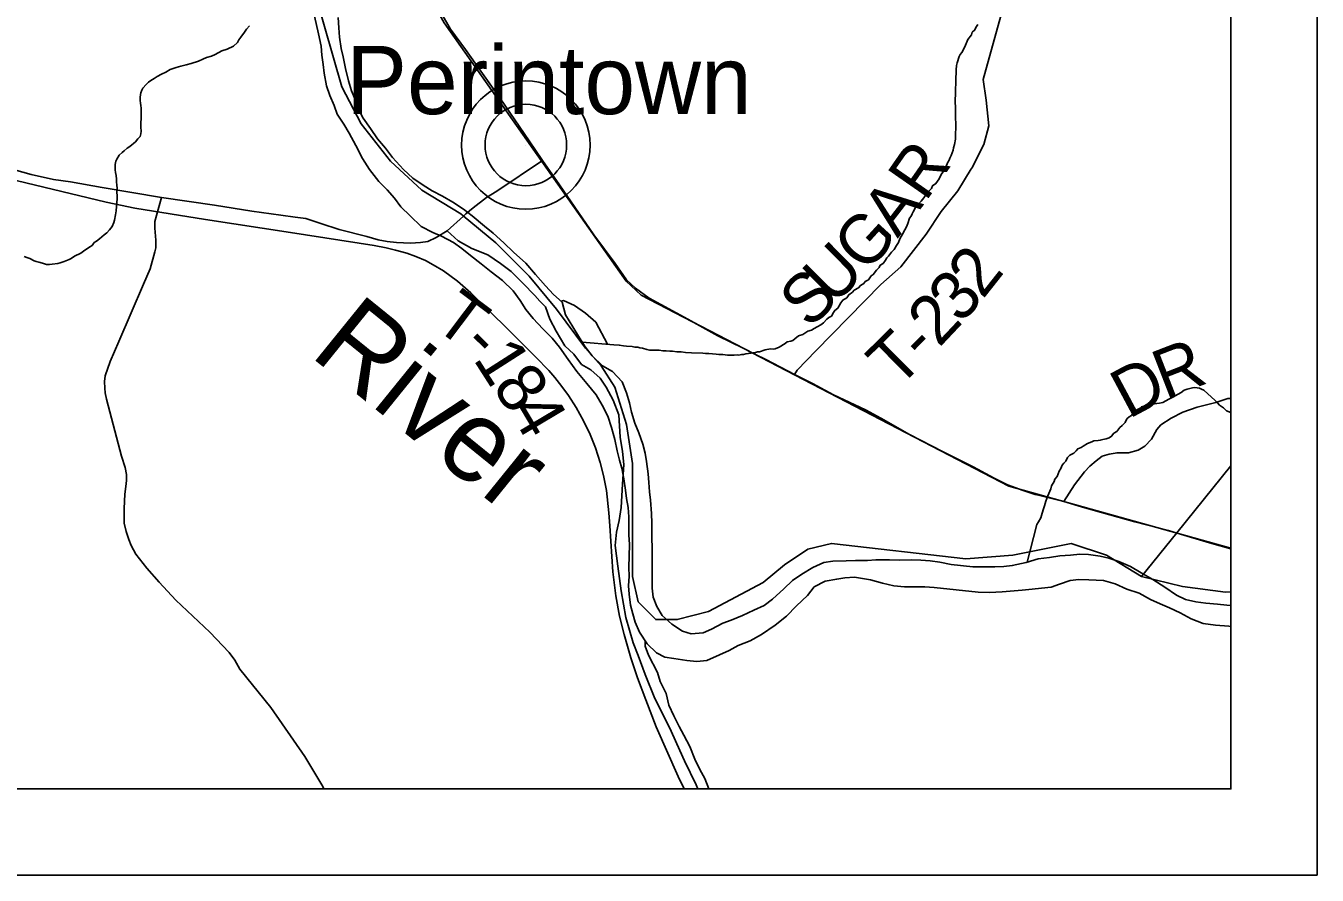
# Model space of a CAD drawing. Extents: x 44.2 to 78.2, y 4.5 to 26.5.
# Drawn here: x 51.74 to 53.236, y 18.501 to 19.485 of the extents above; entities that cross this region are included whole.
import ezdxf

# ---------------------------------------------------------------- set-up
doc = ezdxf.new("R2010")
doc.units = 0
for name, color, linetype in [('GM_X_County_Road', 7, 'Continuous'), ('GM_X_Major_River', 7, 'Continuous'), ('GM_X_Major_River_Text', 7, 'Continuous'), ('GM_X_Minor_River', 7, 'Continuous'), ('GM_X_Rail_Line', 7, 'Continuous'), ('GM_X_Township_Road', 7, 'Continuous'), ('GM_X_Township_Road_Text', 7, 'Continuous'), ('GM_X_Unincorporated', 7, 'Continuous'), ('GM_X_Unincorporated_Location', 7, 'Continuous'), ('GM_X_Unincorporated_Text', 7, 'Continuous'), ('GM_X_US_Route', 7, 'Continuous'), ('SH_Cut_Line', 7, 'Continuous'), ('SH_Data', 7, 'Continuous')]:
    doc.layers.add(name, color=color, linetype=linetype)

msp = doc.modelspace()

# ---------------------------------------------------------------- linework, layer by layer
at = {"layer": 'GM_X_County_Road'}
for points in [[(52.2501, 19.2672), (52.2583, 19.2743), (52.2739, 19.2861), (52.2858, 19.2937), (52.3386, 19.3291)], [(51.7177, 19.3209), (51.7466, 19.3127), (51.7726, 19.3069), (51.7922, 19.3043), (51.8287, 19.2979), (51.8976, 19.2863), (51.959, 19.2772), (52.0023, 19.2703), (52.0358, 19.2658), (52.0524, 19.2635), (52.0645, 19.2618), (52.0821, 19.2562), (52.1033, 19.2492), (52.1352, 19.2409), (52.1484, 19.2372), (52.1589, 19.2351), (52.1696, 19.234), (52.1858, 19.2333), (52.1974, 19.2342), (52.2058, 19.2353), (52.2157, 19.24), (52.2283, 19.2477), (52.2471, 19.2647), (52.2501, 19.2672)], [(52.0854, 18.6014), (52.0844, 18.604), (52.0635, 18.639), (52.0242, 18.6956), (51.9884, 18.7401), (51.9826, 18.7505), (51.976, 18.7594), (51.9535, 18.783), (51.9143, 18.8199), (51.8948, 18.8409), (51.8804, 18.8568), (51.8679, 18.873), (51.8625, 18.8833), (51.8597, 18.8902), (51.8565, 18.8994), (51.8544, 18.9089), (51.8545, 18.926), (51.8549, 18.9427), (51.8562, 18.9517), (51.8572, 18.9586), (51.857, 18.9654), (51.8553, 18.9734), (51.8514, 18.9867), (51.8337, 19.0528), (51.8324, 19.06), (51.8318, 19.0653), (51.8316, 19.0733), (51.8325, 19.0797), (51.8382, 19.0963), (51.8482, 19.1196), (51.8767, 19.186), (51.8843, 19.2037), (51.8897, 19.2233), (51.8909, 19.2278), (51.8908, 19.2369), (51.89, 19.2509), (51.8898, 19.2585), (51.8976, 19.2863)]]:
    msp.add_lwpolyline(points, dxfattribs=at)
at = {"layer": 'GM_X_Major_River'}
for points in [[(52.0746, 19.4963), (52.0795, 19.4757), (52.0823, 19.4615), (52.0833, 19.4512), (52.0846, 19.4402), (52.0859, 19.4303), (52.0887, 19.4154), (52.0926, 19.4043), (52.0974, 19.3928), (52.101, 19.3829), (52.1087, 19.3713), (52.115, 19.3606), (52.1227, 19.3464), (52.1304, 19.3314), (52.1385, 19.3188), (52.1492, 19.3049), (52.1589, 19.2952), (52.1674, 19.2856), (52.1748, 19.2756), (52.1856, 19.2651), (52.1983, 19.2528), (52.2118, 19.2457), (52.2219, 19.2414), (52.2358, 19.2343), (52.2455, 19.2273), (52.2552, 19.2192), (52.2679, 19.2095), (52.2795, 19.2002), (52.2926, 19.1901), (52.3049, 19.1781), (52.313, 19.1669), (52.3196, 19.1565), (52.3278, 19.1461), (52.3393, 19.1342), (52.3501, 19.1234), (52.3586, 19.113), (52.3686, 19.0987), (52.3786, 19.0849), (52.3901, 19.071), (52.4008, 19.0579), (52.4078, 19.0456), (52.4144, 19.033), (52.4187, 19.02), (52.4226, 19.0058), (52.4254, 18.9928), (52.4279, 18.9821), (52.4307, 18.9726), (52.4328, 18.9604), (52.4348, 18.9474), (52.4362, 18.9375), (52.4379, 18.9272), (52.4388, 18.9165), (52.4386, 18.907), (52.4388, 18.8956), (52.4394, 18.8842), (52.4389, 18.8579), (52.4391, 18.8477), (52.4385, 18.8366), (52.4391, 18.8267), (52.4408, 18.8142), (52.4432, 18.8042), (52.4461, 18.7943), (52.4512, 18.7828), (52.46, 18.7694), (52.4708, 18.7589), (52.4806, 18.7538), (52.4908, 18.7525), (52.5059, 18.75), (52.5176, 18.7487), (52.529, 18.75), (52.5439, 18.7566), (52.555, 18.7618), (52.5653, 18.7673), (52.5794, 18.7728), (52.5924, 18.7802), (52.6081, 18.791), (52.6212, 18.8015), (52.6328, 18.8135), (52.6455, 18.8255), (52.6532, 18.8352), (52.6662, 18.8419)], [(52.1022, 19.4947), (52.1028, 19.4829), (52.1037, 19.4719), (52.1057, 19.4589), (52.1078, 19.449), (52.1106, 19.4356), (52.1142, 19.4215), (52.1177, 19.4096), (52.1217, 19.3997), (52.1261, 19.3878), (52.1312, 19.3782), (52.1397, 19.3663), (52.1478, 19.354), (52.1571, 19.3432), (52.1652, 19.3324), (52.1778, 19.3185), (52.1887, 19.3088), (52.2006, 19.3007), (52.2111, 19.294), (52.2231, 19.2878), (52.2351, 19.2807), (52.2471, 19.2726), (52.2572, 19.2652), (52.2717, 19.2532), (52.2818, 19.245), (52.2941, 19.2338), (52.3053, 19.223), (52.3195, 19.2102), (52.3306, 19.1971), (52.3421, 19.184), (52.3514, 19.1739), (52.3614, 19.1649), (52.3654, 19.1505), (52.3738, 19.1363), (52.3815, 19.1236), (52.3882, 19.1133), (52.3963, 19.1029), (52.4082, 19.0913), (52.4199, 19.0846), (52.431, 19.0726), (52.4361, 19.06), (52.4397, 19.0485), (52.4417, 19.0375), (52.4457, 19.0249), (52.4504, 19.0138), (52.4551, 19.0007), (52.4575, 18.9901), (52.4593, 18.9805), (52.4613, 18.9664), (52.4619, 18.9561), (52.4628, 18.9455), (52.4638, 18.9356), (52.465, 18.9203), (52.4652, 18.9089)], [(52.4652, 18.9089), (52.4653, 18.8933), (52.4658, 18.8788), (52.4656, 18.8693), (52.4658, 18.8583), (52.4656, 18.845), (52.4657, 18.8339), (52.4671, 18.8233), (52.471, 18.8126), (52.4773, 18.8022), (52.4885, 18.7921), (52.5008, 18.7839), (52.511, 18.7811), (52.525, 18.782), (52.5346, 18.7865), (52.5476, 18.7931), (52.5571, 18.7968), (52.5705, 18.8023), (52.5835, 18.8082), (52.5953, 18.8137), (52.6053, 18.8211), (52.6184, 18.8331), (52.6284, 18.8428), (52.6391, 18.8499), (52.6518, 18.8577), (52.6647, 18.8636), (52.675, 18.865), (52.6905, 18.8655), (52.7011, 18.8657), (52.7151, 18.8659), (52.7246, 18.8665), (52.7405, 18.8666), (52.7519, 18.8664), (52.7655, 18.8666), (52.7769, 18.8664), (52.7875, 18.8655), (52.7988, 18.8638), (52.812, 18.8613), (52.837, 18.8587), (52.848, 18.8585), (52.8627, 18.8586), (52.873, 18.8589), (52.8828, 18.8599), (52.8988, 18.8634), (52.9129, 18.8678), (52.9258, 18.8695), (52.9379, 18.8712), (52.9501, 18.8721), (52.9611, 18.8731), (52.9709, 18.8729), (52.9845, 18.8708), (52.9947, 18.8684), (53.006, 18.8648), (53.0195, 18.8589), (53.0319, 18.8515), (53.0454, 18.844), (53.0593, 18.8351), (53.0731, 18.8257), (53.0832, 18.8206), (53.0953, 18.8181), (53.107, 18.8164), (53.1203, 18.8151), (53.1312, 18.8142), (53.1359, 18.8137)], [(52.6662, 18.8419), (52.6795, 18.8443), (52.689, 18.8457), (52.7, 18.8467), (52.7185, 18.8434), (52.7325, 18.8397), (52.7457, 18.8365), (52.7578, 18.8355), (52.7699, 18.8353), (52.7816, 18.8355), (52.7922, 18.8346), (52.8433, 18.8293), (52.8565, 18.8287), (52.8709, 18.8296), (52.885, 18.8309), (52.8944, 18.8315), (52.9058, 18.8325), (52.9168, 18.8338), (52.9278, 18.8348), (52.9374, 18.8385), (52.9499, 18.8425), (52.9598, 18.8438), (52.9715, 18.8436), (52.9886, 18.8426), (53.0018, 18.839), (53.0153, 18.8327), (53.0296, 18.8279), (53.0427, 18.8205), (53.054, 18.8157), (53.0649, 18.811), (53.0773, 18.8051), (53.09, 18.7981), (53.1039, 18.7929), (53.1183, 18.7908), (53.1334, 18.7898), (53.1359, 18.7894)]]:
    msp.add_lwpolyline(points, dxfattribs=at)
at = {"layer": 'GM_X_Minor_River'}
for points in [[(52.7743, 19.2786), (52.7771, 19.2819), (52.7802, 19.286), (52.7845, 19.292), (52.7892, 19.2968), (52.7904, 19.2998), (52.7943, 19.3024), (52.7963, 19.305), (52.7982, 19.3079), (52.8006, 19.3128), (52.8034, 19.3173), (52.8042, 19.3195), (52.807, 19.324), (52.8078, 19.3263), (52.8098, 19.3296), (52.8106, 19.3319), (52.8122, 19.3349), (52.8143, 19.3409), (52.8147, 19.3436), (52.816, 19.3477), (52.8169, 19.3537), (52.8174, 19.3731), (52.8171, 19.3769), (52.8172, 19.3799), (52.817, 19.3871), (52.8171, 19.3913), (52.8168, 19.3962), (52.8178, 19.4342), (52.8183, 19.4391), (52.8191, 19.4421), (52.8212, 19.4496), (52.8224, 19.4519), (52.8244, 19.4541), (52.828, 19.4608), (52.8312, 19.4691), (52.8355, 19.4747), (52.8364, 19.4777), (52.8391, 19.4799), (52.8415, 19.4844), (52.843, 19.4866)], [(51.9994, 19.4852), (51.9959, 19.4811), (51.9935, 19.4777), (51.9896, 19.4718), (51.9872, 19.4688), (51.9856, 19.4658), (51.981, 19.4614), (51.9737, 19.4581), (51.9675, 19.456), (51.9595, 19.4517), (51.9556, 19.4499), (51.9495, 19.4485), (51.9453, 19.4464), (51.9403, 19.4442), (51.9319, 19.4414), (51.9261, 19.44), (51.92, 19.4383), (51.9146, 19.4369), (51.9112, 19.4355), (51.9077, 19.4344), (51.9024, 19.4315), (51.8977, 19.429), (51.8927, 19.4265), (51.8889, 19.4239), (51.885, 19.4218), (51.8823, 19.4199), (51.8796, 19.4173), (51.8761, 19.4129), (51.8749, 19.4106), (51.8736, 19.4076), (51.8732, 19.4054), (51.8727, 19.402), (51.873, 19.3985), (51.8733, 19.3955), (51.8736, 19.3928), (51.8739, 19.3898), (51.8739, 19.386), (51.8741, 19.3826), (51.8738, 19.3678), (51.874, 19.3629), (51.8736, 19.3598), (51.8727, 19.3568), (51.87, 19.3542), (51.8676, 19.3509), (51.8607, 19.3454), (51.8576, 19.3432), (51.8545, 19.3402), (51.8521, 19.3384), (51.8486, 19.3351), (51.8459, 19.3306), (51.8447, 19.3283), (51.8438, 19.3246), (51.8437, 19.3215), (51.844, 19.3181), (51.8443, 19.3151), (51.845, 19.3116), (51.8453, 19.3074), (51.8456, 19.304), (51.8459, 19.301), (51.8461, 19.2968), (51.846, 19.2919), (51.8463, 19.2885), (51.8462, 19.2847), (51.8457, 19.2805), (51.8456, 19.2759), (51.8451, 19.2707), (51.8442, 19.2661), (51.8433, 19.2601), (51.8425, 19.2574), (51.8405, 19.2526), (51.8373, 19.2489), (51.8342, 19.2455), (51.8311, 19.2429), (51.8257, 19.2382), (51.8222, 19.2356), (51.8195, 19.2341), (51.8171, 19.2308), (51.8144, 19.229), (51.8074, 19.2242)], [(52.3847, 19.1187), (52.4215, 19.1156), (52.4276, 19.1154), (52.4325, 19.1145), (52.4359, 19.1141), (52.4427, 19.1135), (52.4458, 19.113), (52.4492, 19.1129), (52.4514, 19.1121), (52.4545, 19.1117), (52.4597, 19.1104), (52.4628, 19.1096), (52.4738, 19.1093), (52.4783, 19.1088), (52.4821, 19.1087), (52.4863, 19.1082), (52.4893, 19.1081), (52.4942, 19.1076), (52.4995, 19.1075), (52.5045, 19.1069), (52.5113, 19.1064), (52.5246, 19.106), (52.5276, 19.1056), (52.5314, 19.1055), (52.5356, 19.105), (52.5397, 19.1049), (52.5431, 19.1044), (52.5477, 19.1043), (52.553, 19.1038), (52.5606, 19.1036), (52.564, 19.1039), (52.5663, 19.1038), (52.5694, 19.1045), (52.5716, 19.1044), (52.5743, 19.1051), (52.577, 19.1054), (52.5804, 19.1061), (52.5827, 19.1064), (52.5854, 19.1067), (52.5877, 19.1074), (52.59, 19.1077), (52.5968, 19.1098), (52.6026, 19.1108), (52.606, 19.1107), (52.6083, 19.1111), (52.6129, 19.1128), (52.6198, 19.1172), (52.6221, 19.119), (52.6263, 19.1197), (52.6286, 19.1208), (52.631, 19.1226), (52.6352, 19.1259), (52.6402, 19.1277), (52.646, 19.1313), (52.6502, 19.1327), (52.6533, 19.1346), (52.6568, 19.1364), (52.661, 19.1389), (52.6641, 19.1411), (52.668, 19.1455), (52.6703, 19.1474), (52.6734, 19.1488), (52.6758, 19.1529), (52.6774, 19.1555), (52.6809, 19.1581), (52.6841, 19.1641), (52.6864, 19.1674), (52.691, 19.17), (52.6934, 19.1737), (52.6977, 19.1766), (52.6996, 19.1789), (52.7046, 19.1818), (52.707, 19.1844), (52.7108, 19.1865), (52.7124, 19.1888), (52.7163, 19.191), (52.7194, 19.1954), (52.7217, 19.1969), (52.7257, 19.2021), (52.7288, 19.205), (52.7296, 19.2077), (52.7331, 19.2099), (52.7358, 19.2136), (52.7374, 19.2162), (52.7394, 19.2184), (52.7429, 19.2229), (52.746, 19.2262), (52.7488, 19.2307), (52.7512, 19.2341), (52.7524, 19.2382), (52.7556, 19.2438), (52.7584, 19.2487), (52.7604, 19.2524), (52.762, 19.2562), (52.7637, 19.2622), (52.7656, 19.2648), (52.7668, 19.2674), (52.768, 19.2697), (52.7704, 19.2738), (52.7708, 19.276), (52.7743, 19.2786)], [(51.8074, 19.2242), (51.804, 19.2216), (51.7967, 19.2184), (51.7928, 19.2155), (51.7905, 19.2144), (51.7847, 19.2123), (51.7801, 19.2105), (51.7775, 19.2098), (51.771, 19.2092), (51.7675, 19.2086), (51.7645, 19.2086), (51.7596, 19.2103), (51.7555, 19.2112), (51.7524, 19.212), (51.7502, 19.2128), (51.7449, 19.2156), (51.7415, 19.2168), (51.7385, 19.218)], [(52.36, 19.1662), (52.363, 19.1668), (52.3757, 19.1612), (52.3884, 19.1523), (52.4007, 19.1418), (52.4142, 19.1162)], [(52.9002, 18.8639), (52.9111, 18.9077), (52.9131, 18.9107), (52.9159, 18.9152), (52.9167, 18.9178), (52.9184, 18.9246), (52.92, 18.9291), (52.9217, 18.9344), (52.9241, 18.9408), (52.925, 18.9434), (52.9274, 18.9487), (52.9282, 18.9524), (52.9314, 18.9573), (52.9322, 18.9599), (52.9346, 18.9633), (52.937, 18.9693), (52.939, 18.9723), (52.9406, 18.9764), (52.9426, 18.9786), (52.9449, 18.9808), (52.9469, 18.985), (52.9496, 18.9879), (52.9539, 18.9901), (52.9566, 18.9927), (52.9586, 18.9953), (52.9624, 18.9967), (52.9647, 18.9982), (52.9697, 19.0014), (52.9751, 19.0032), (52.9774, 19.0043), (52.9823, 19.0049), (52.9846, 19.0052), (52.9877, 19.0059), (52.9915, 19.0066), (52.995, 19.008), (52.9977, 19.0098), (53.0004, 19.0132), (53.0039, 19.0153), (53.0074, 19.0198), (53.0101, 19.022), (53.0136, 19.0257), (53.0156, 19.0298), (53.018, 19.0321), (53.0207, 19.0339), (53.0235, 19.038), (53.0258, 19.0398), (53.0292, 19.0409), (53.0323, 19.0438), (53.035, 19.0445), (53.0373, 19.0452), (53.04, 19.0463), (53.0438, 19.0466), (53.0476, 19.0472), (53.0499, 19.0475), (53.0533, 19.0482), (53.0572, 19.0489), (53.0641, 19.0525), (53.0687, 19.055), (53.0749, 19.0586), (53.0783, 19.0604), (53.0818, 19.063), (53.0853, 19.0644), (53.0914, 19.0658), (53.0941, 19.0661), (53.0967, 19.066), (53.0997, 19.0656), (53.102, 19.0644), (53.1046, 19.0632), (53.1091, 19.0589), (53.1131, 19.0554), (53.1176, 19.0511), (53.1206, 19.0483), (53.1228, 19.0456), (53.125, 19.0441), (53.1273, 19.0425), (53.131, 19.0393), (53.1359, 19.0373), (53.1359, 19.0373)], [(52.4577, 18.7729), (52.4578, 18.7666), (52.4617, 18.7563), (52.4719, 18.736), (52.4751, 18.7257), (52.482, 18.7119), (52.4851, 18.6982), (52.491, 18.6859), (52.4971, 18.6737), (52.5026, 18.6637), (52.5092, 18.6503), (52.5153, 18.6358), (52.5211, 18.6239), (52.5266, 18.6132), (52.5313, 18.6014)]]:
    msp.add_lwpolyline(points, dxfattribs=at)
at = {"layer": 'GM_X_Rail_Line'}
for points in [[(52.0567, 19.5883), (52.1063, 19.4143), (52.1289, 19.3714), (52.1628, 19.3285), (52.1989, 19.2946), (52.2441, 19.2675), (52.2468, 19.2652), (52.2848, 19.2336), (52.3232, 19.1952), (52.3548, 19.1568), (52.3887, 19.1116), (52.4067, 19.0912), (52.4226, 19.0664), (52.4361, 19.0234), (52.4429, 18.9783), (52.4429, 18.8472), (52.4496, 18.8179), (52.47, 18.7975), (52.4948, 18.7975), (52.531, 18.8066), (52.5942, 18.8404), (52.6191, 18.8608), (52.6462, 18.8789), (52.6733, 18.8856), (52.8291, 18.8676), (52.8834, 18.8721), (52.9511, 18.8856), (52.9918, 18.8721), (53.0324, 18.8472), (53.0734, 18.898), (53.1359, 18.9756), (53.1359, 25.4014)], [(53.1359, 18.8803), (52.8787, 18.9518), (52.4529, 19.1732), (52.4355, 19.1892), (52.2249, 19.4887), (52.1626, 19.5993), (52.0324, 19.7548), (51.9429, 19.8757), (51.918, 19.9004), (51.8875, 19.9114), (51.8322, 19.9117), (51.7576, 19.9172), (51.6529, 19.9117)], [(48.642, 18.6014), (53.1359, 18.6014), (53.1359, 18.8297), (53.1296, 18.8292), (53.0799, 18.8359), (53.0324, 18.8472), (52.9918, 18.8721), (52.9511, 18.8856), (52.8834, 18.8721), (52.8291, 18.8676), (52.6733, 18.8856), (52.6462, 18.8789), (52.6191, 18.8608), (52.5942, 18.8404), (52.531, 18.8066), (52.4948, 18.7975), (52.47, 18.7975), (52.4496, 18.8179), (52.4429, 18.8472), (52.4429, 18.9783), (52.4361, 19.0234), (52.4226, 19.0664), (52.4067, 19.0912), (52.3887, 19.1116), (52.3548, 19.1568), (52.3232, 19.1952), (52.2848, 19.2336), (52.2468, 19.2652), (52.2441, 19.2675), (52.1989, 19.2946), (52.1628, 19.3285), (52.1289, 19.3714), (52.1063, 19.4143), (52.0567, 19.5883)], [(51.3792, 19.39), (51.8335, 19.2809), (51.8666, 19.274), (51.9485, 19.2609), (52.0469, 19.2457), (52.1439, 19.2305), (52.1578, 19.2278), (52.1687, 19.2254), (52.1815, 19.2219), (52.1921, 19.2179), (52.2031, 19.2132), (52.2122, 19.2084), (52.2243, 19.2013), (52.2403, 19.1893), (52.2557, 19.176), (52.299, 19.1335), (52.3312, 19.1015), (52.3459, 19.086), (52.353, 19.0777), (52.3613, 19.0674), (52.3688, 19.0569), (52.3778, 19.0429), (52.3864, 19.0277), (52.394, 19.0119), (52.4001, 18.9962), (52.4057, 18.9793), (52.4095, 18.9644), (52.413, 18.9468), (52.4157, 18.9212), (52.4168, 18.9061), (52.4203, 18.8526), (52.4238, 18.825), (52.4281, 18.8014), (52.4333, 18.78), (52.4412, 18.753), (52.4489, 18.73), (52.4583, 18.7043), (52.4705, 18.6734), (52.4959, 18.6158), (52.5029, 18.6014)]]:
    msp.add_lwpolyline(points, dxfattribs=at)
msp.add_lwpolyline([(53.1359, 18.8297), (53.1359, 18.9756), (53.0734, 18.898), (53.0324, 18.8472), (53.0799, 18.8359), (53.1296, 18.8292)], close=True, dxfattribs=at)
at = {"layer": 'GM_X_Township_Road'}
for points in [[(52.6304, 19.0813), (52.6336, 19.0862), (52.6552, 19.1086), (52.7307, 19.1855), (52.7536, 19.2061), (52.783, 19.2436), (52.8004, 19.2699), (52.8199, 19.2941), (52.8353, 19.3196), (52.8358, 19.3203), (52.8498, 19.3476), (52.8557, 19.3693), (52.8525, 19.3988), (52.8491, 19.4228), (52.8695, 19.4965), (52.8768, 19.5163), (52.8829, 19.541), (52.8868, 19.5707), (52.8861, 19.5848), (52.8855, 19.5964)], [(52.2283, 19.2477), (52.241, 19.236), (52.2569, 19.2272), (52.2756, 19.22), (52.2903, 19.2099), (52.3026, 19.2006), (52.316, 19.1872), (52.3298, 19.1727), (52.3358, 19.1661), (52.3421, 19.1598), (52.3474, 19.1455), (52.3545, 19.1314), (52.3647, 19.1145), (52.3751, 19.1048), (52.3839, 19.093), (52.3946, 19.0865), (52.4056, 19.0771), (52.4126, 19.0665), (52.4207, 19.0515), (52.4272, 19.0344), (52.4288, 19.0087), (52.4313, 18.992), (52.4329, 18.977), (52.4313, 18.9541), (52.4298, 18.9272), (52.4274, 18.9123), (52.4245, 18.8985), (52.4228, 18.8832), (52.4261, 18.8591), (52.4299, 18.8309), (52.4353, 18.7998), (52.4436, 18.7704), (52.4494, 18.7558), (52.4577, 18.7339), (52.4689, 18.7061), (52.4863, 18.6716), (52.4942, 18.6534), (52.5033, 18.6339), (52.5166, 18.6061), (52.5187, 18.6014)], [(52.9424, 18.9342), (52.9549, 18.9535), (52.9666, 18.9684), (52.9725, 18.9751), (52.9798, 18.9814), (52.9867, 18.9866), (52.9951, 18.989), (53.0042, 18.9907), (53.0172, 18.9905), (53.0286, 18.9935), (53.0362, 18.9981), (53.0439, 19.0063), (53.0503, 19.0177), (53.0549, 19.0229), (53.0669, 19.0306), (53.0802, 19.0377), (53.0967, 19.0435), (53.1186, 19.0489), (53.1324, 19.0535), (53.1359, 19.0535)]]:
    msp.add_lwpolyline(points, dxfattribs=at)
at = {"layer": 'GM_X_Unincorporated'}
for radius in [0.0744, 0.0472]:
    msp.add_circle((52.3195, 19.347), radius, dxfattribs=at)
at = {"layer": 'GM_X_Unincorporated_Location'}
msp.add_line((52.3195, 19.347), (52.3195, 19.347), dxfattribs=at)
at = {"layer": 'GM_X_US_Route'}
msp.add_line((52.9132, 18.9415), (52.9424, 18.9342), dxfattribs=at)
for points in [[(52.1689, 19.5951), (52.1843, 19.5689), (52.2016, 19.5381), (52.2128, 19.5146), (52.2321, 19.4812), (52.2495, 19.4575), (52.2541, 19.451)], [(52.2541, 19.451), (52.29, 19.4007), (52.3235, 19.3519), (52.3386, 19.3291), (52.3585, 19.3011), (52.3982, 19.2431), (52.423, 19.2098), (52.4362, 19.191), (52.4464, 19.1812), (52.4623, 19.1698), (52.5071, 19.1453), (52.5417, 19.1259), (52.571, 19.1118), (52.5856, 19.1046)], [(52.5856, 19.1046), (52.5974, 19.0987), (52.6304, 19.0813)], [(52.6304, 19.0813), (52.6515, 19.0708), (52.6756, 19.0579), (52.7128, 19.0402), (52.7306, 19.0307), (52.7636, 19.0116), (52.802, 18.9921), (52.8373, 18.9744), (52.8617, 18.9611), (52.8771, 18.9535), (52.8952, 18.9469), (52.9093, 18.9424), (52.9132, 18.9415)], [(52.9424, 18.9342), (52.9667, 18.9268), (52.9712, 18.9255)], [(52.9712, 18.9255), (52.9766, 18.924), (53.0248, 18.9107), (53.0636, 18.9005), (53.0736, 18.8974), (53.1112, 18.8862), (53.1359, 18.8795)]]:
    msp.add_lwpolyline(points, dxfattribs=at)
at = {"layer": 'SH_Cut_Line'}
msp.add_lwpolyline([(48.642, 18.6014), (53.1359, 18.6014), (53.1359, 25.4014)], dxfattribs=at)
at = {"layer": 'SH_Data'}
for p, q in [((53.2359, 25.5014), (53.2359, 18.5014)), ((53.1359, 25.4014), (53.1359, 18.6014)), ((46.3359, 18.6014), (53.1359, 18.6014)), ((46.2359, 18.5014), (53.2359, 18.5014))]:
    msp.add_line(p, q, dxfattribs=at)

# ---------------------------------------------------------------- texts
at = {"layer": 'GM_X_Major_River_Text'}
msp.add_text('River', height=0.0947, rotation=320.9932, dxfattribs=at).set_placement((52.0677, 19.1038))
at = {"layer": 'GM_X_Township_Road_Text'}
for s, rotation, p in [('R', 55.1496, (52.7823, 19.2803)), ('A', 52.3711, (52.75, 19.2383)), ('G', 47.5951, (52.7129, 19.1974)), ('U', 44.8581, (52.6754, 19.16)), ('2', 51.66, (52.8485, 19.1675)), ('S', 44.7346, (52.6481, 19.1329)), ('3', 48.9024, (52.8236, 19.1388)), ('T', 323.0512, (52.2107, 19.1374)), ('2', 46.7083, (52.798, 19.1116)), ('-', 315.3753, (52.2432, 19.1132)), ('T', 44.7242, (52.7499, 19.0636)), ('-', 45.2404, (52.7805, 19.0939)), ('1', 302.6249, (52.2577, 19.0994)), ('R', 21.2477, (53.0598, 19.052)), ('8', 306.9247, (52.2792, 19.0661)), ('D', 28.1438, (53.0174, 19.0292)), ('4', 300.746, (52.2993, 19.0394))]:
    msp.add_text(s, height=0.0568, rotation=rotation, dxfattribs=at).set_placement(p)
at = {"layer": 'GM_X_Unincorporated_Text'}
msp.add_text('Perintown', height=0.07898, rotation=0, dxfattribs=at).set_placement((52.1114, 19.3828))

doc.saveas('drawing.dxf')
